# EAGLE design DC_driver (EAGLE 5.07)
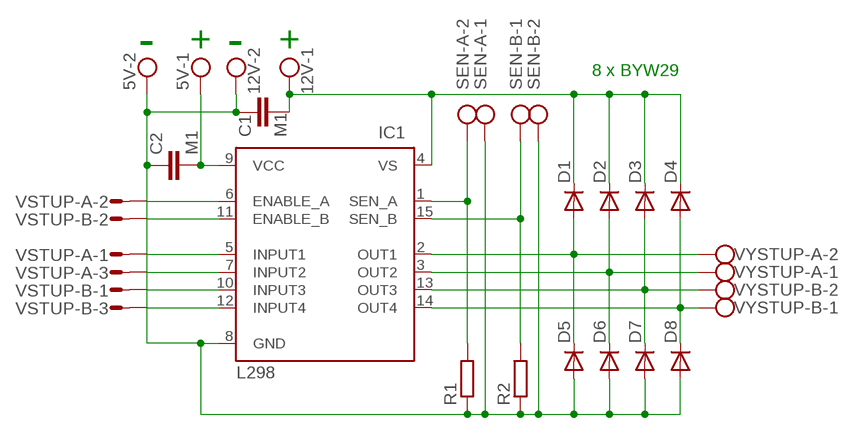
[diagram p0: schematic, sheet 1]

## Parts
5V  W237-102  [W237-102]
12V  W237-102  [W237-102]
C1  M1  C-EU025-025X050  [C025-025X050]
C2  M1  C-EU025-025X050  [C025-025X050]
D1  BYW29  [DO220S]
D2  BYW29  [DO220S]
D3  BYW29  [DO220S]
D4  BYW29  [DO220S]
D5  BYW29  [DO220S]
D6  BYW29  [DO220S]
D7  BYW29  [DO220S]
D8  BYW29  [DO220S]
IC1  L298  [MULTIWATT-15]
R1  R-EU_0411/15  [0411/15]
R2  R-EU_0411/15  [0411/15]
SEN-A  W237-102  [W237-102]
SEN-B  W237-102  [W237-102]
VSTUP-A  M03S  [03P]
VSTUP-B  M03S  [03P]
VYSTUP-A  W237-102  [W237-102]
VYSTUP-B  W237-102  [W237-102]

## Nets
N$1: 12V.1 C1.2 D1.C D2.C D3.C D4.C IC1.4(VS)
N$2: IC1.10(INPUT3) VSTUP-B.1
N$3: IC1.7(INPUT2) VSTUP-A.3
N$4: IC1.5(INPUT1) VSTUP-A.1
N$5: IC1.11(ENABLE_B) VSTUP-B.2
N$6: IC1.6(ENABLE_A) VSTUP-A.2
N$7: IC1.12(INPUT4) VSTUP-B.3
N$9: 5V.2 12V.2 C1.1 C2.1 D5.A D6.A D7.A D8.A IC1.8(GND) R1.1 R2.1 SEN-A.1 SEN-B.2
N$14: IC1.1(SEN_A) R1.2 SEN-A.2
N$15: IC1.15(SEN_B) R2.2 SEN-B.1
N$16: 5V.1 C2.2 IC1.9(VCC)
N$20: D1.A D5.C IC1.2(OUT1) VYSTUP-A.2
N$21: D2.A D6.C IC1.3(OUT2) VYSTUP-A.1
N$22: D3.A D7.C IC1.13(OUT3) VYSTUP-B.2
N$23: D4.A D8.C IC1.14(OUT4) VYSTUP-B.1

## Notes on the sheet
- - | + | - | +
- 8 x BYW29

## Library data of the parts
5V 12V SEN-A SEN-B VYSTUP-A VYSTUP-B = con-wago-500:W237-102: WAGO SCREW CLAMP
C1 C2 = rcl:C-EU: CAPACITOR, European symbol
D1-D8 = diode:BYW29: DIODE
IC1 = st-microelectronics:L298: DUAL FULL-BRIDGE DRIVER
R1 R2 = rcl:R-EU_: RESISTOR, European symbol
VSTUP-A VSTUP-B = con-amp-quick:M03S: AMP QUICK CONNECTOR

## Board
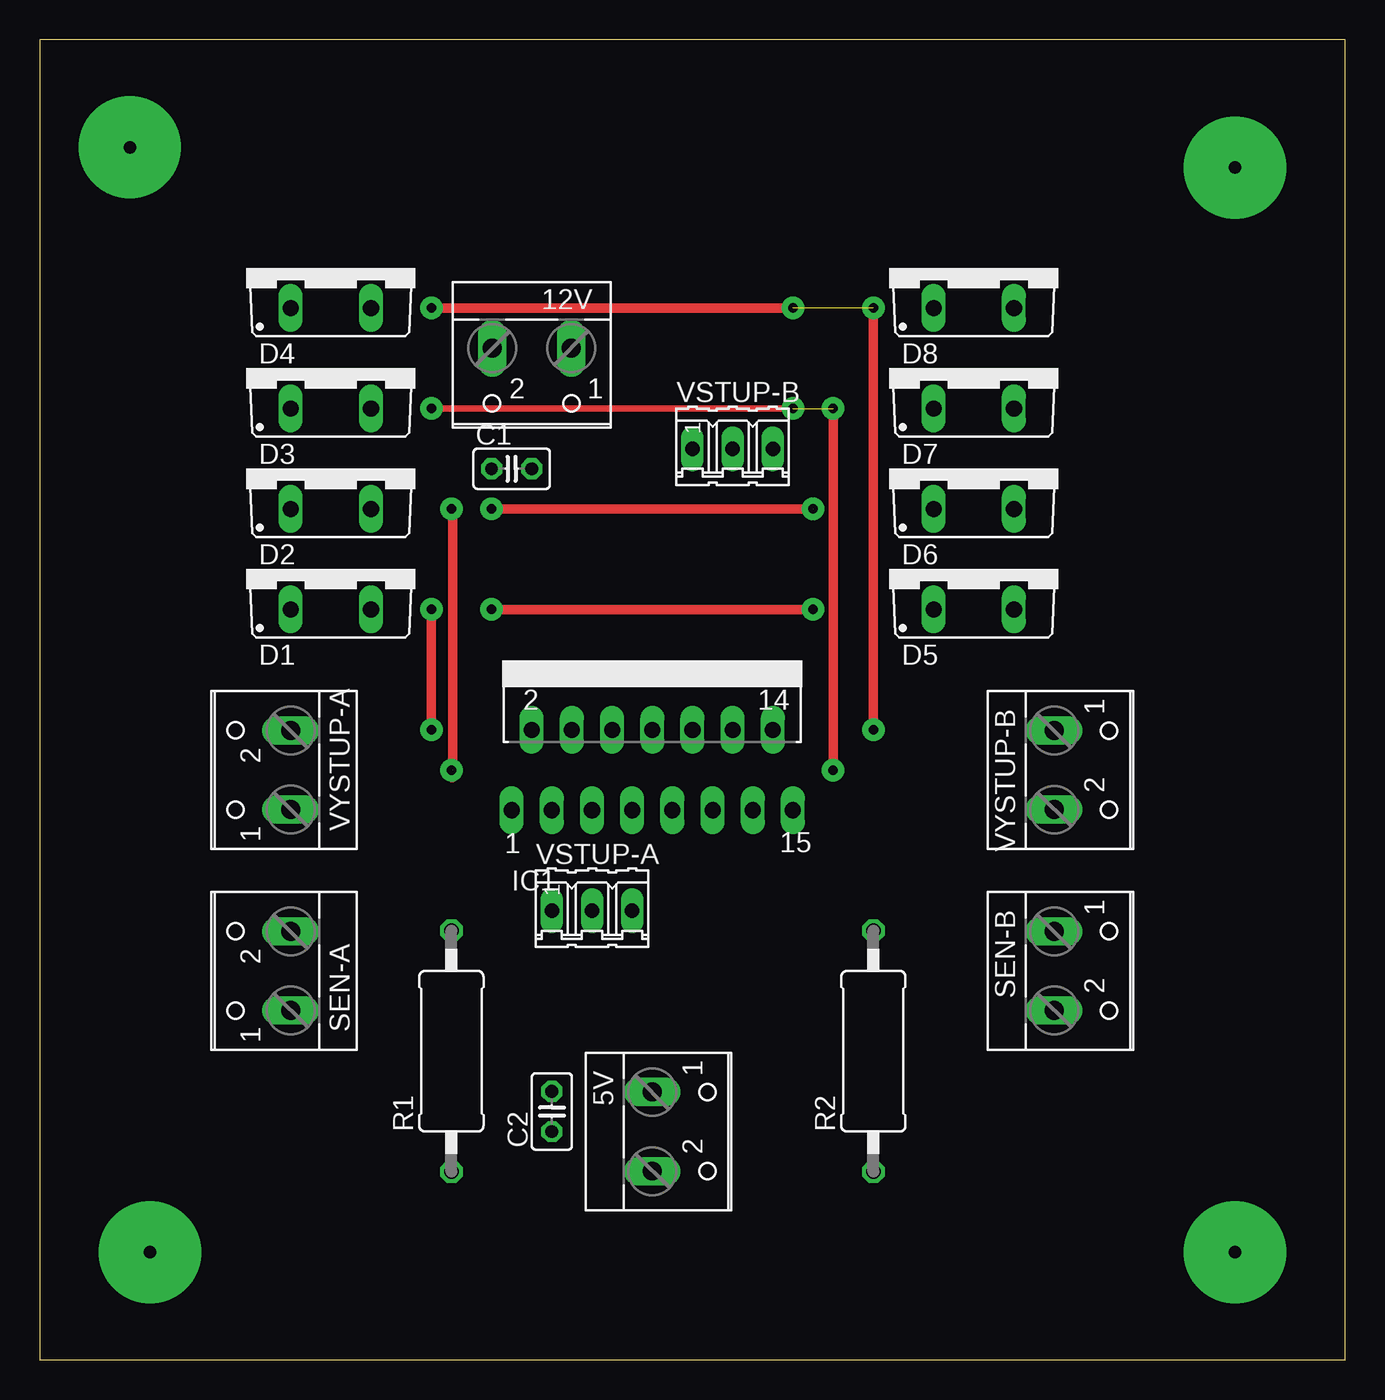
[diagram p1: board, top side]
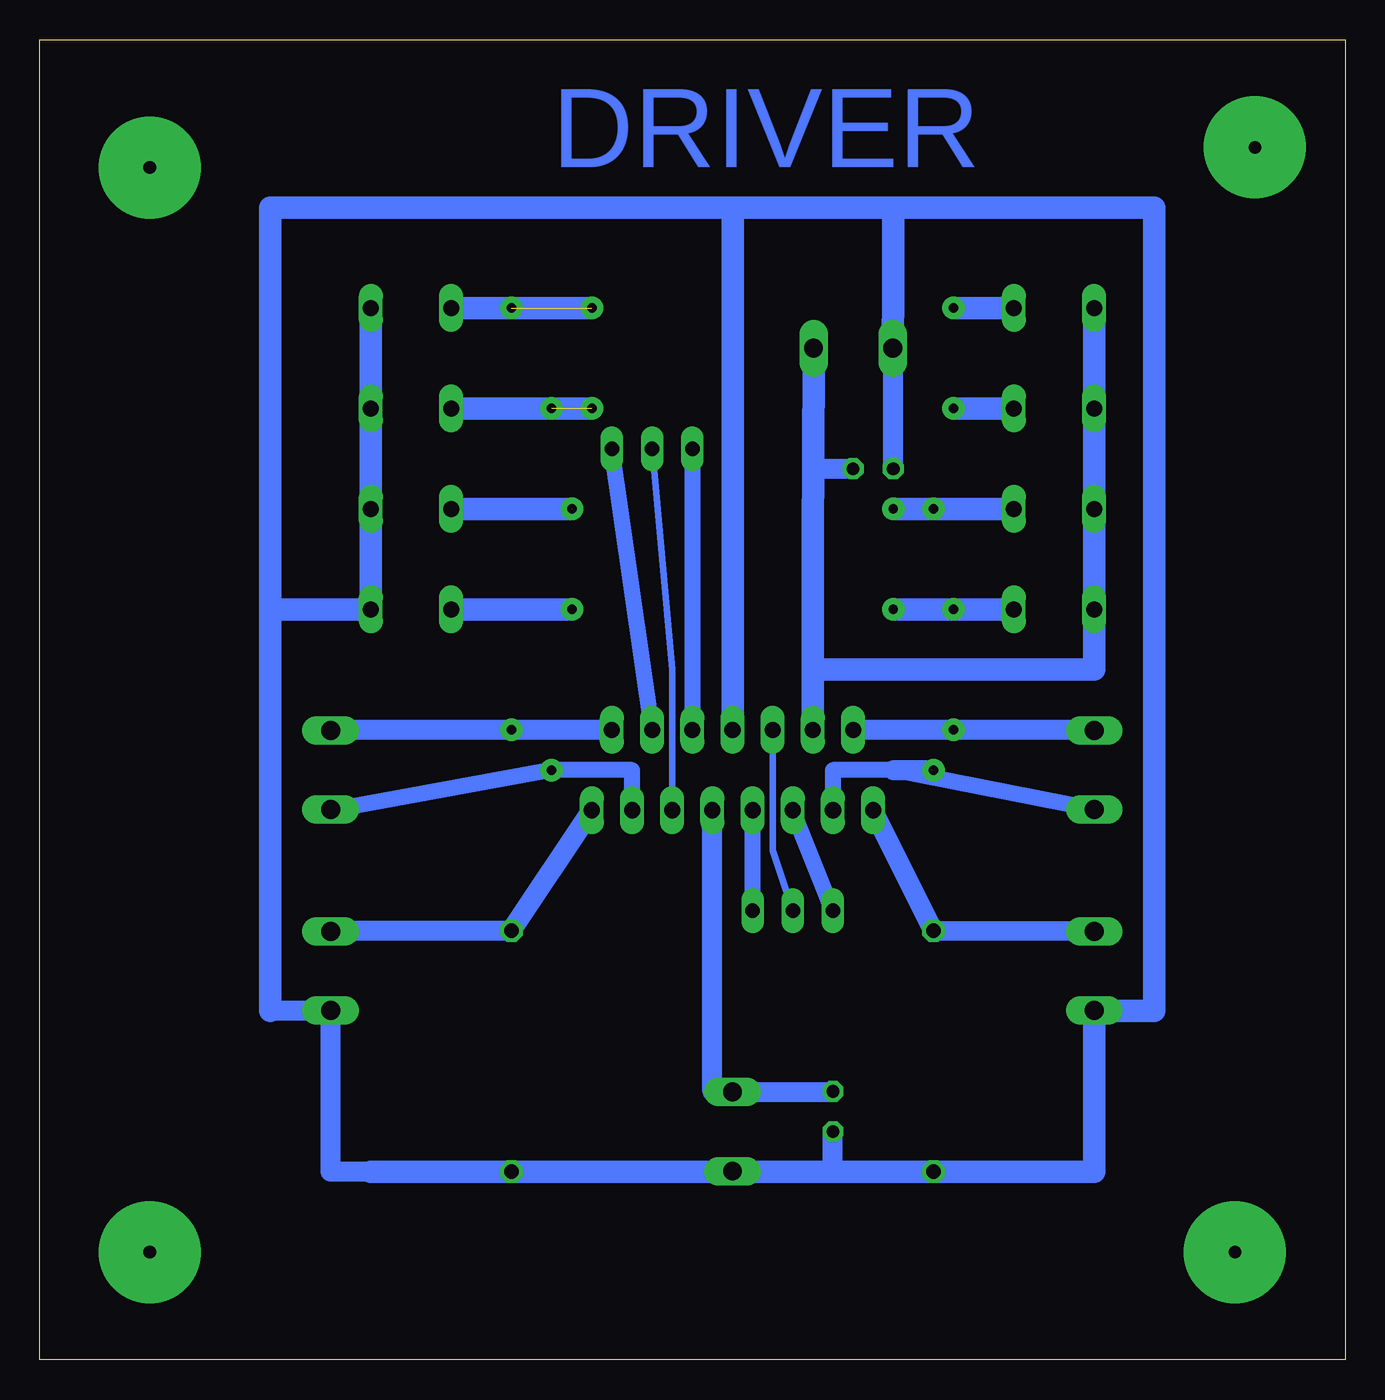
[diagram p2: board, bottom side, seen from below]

Size 82.53 x 83.49 mm. Coordinates in mm from the lower left corner, seen from the top.
Outline: 0,0 82.53,0 82.53,83.49 0,83.49 0,0
Copper layers (1*16): Top 0.035mm / dielectric 1.5mm / Bottom 0.035mm
Design rules "default": minimum track width 10mil, minimum drill 24mil, track to track 8mil, track to pad 8mil, pad to pad 8mil, via to via 8mil, smd to smd 8mil, copper to edge 40mil, drill to drill 8mil, minimum pad ring 10mil, minimum via ring 8mil, stop-mask expansion 4mil, vias tented up to drill 0mil, thermal gap 10mil

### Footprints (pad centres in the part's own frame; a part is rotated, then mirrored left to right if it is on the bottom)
W237-102 = drill 1.194 long: 1 -2.5,-1.27; 2 2.5,-1.27
C025-025X050 = drill 0.813 octagon: 1 -1.27,0; 2 1.27,0
DO220S = drill 1.016 long: A 2.54,-2.54; C -2.54,-2.54
MULTIWATT-15 = drill 1.016 long: 1 -8.89,-7.62; 2 -7.62,-2.54; 3 -6.35,-7.62; 4 -5.08,-2.54; 5 -3.81,-7.62; 6 -2.54,-2.54; 7 -1.27,-7.62; 8 0,-2.54; 9 1.27,-7.62; 10 2.54,-2.54; 11 3.81,-7.62; 12 5.08,-2.54; 13 6.35,-7.62; 14 7.62,-2.54; 15 8.89,-7.62
0411/15 = drill 0.914 octagon: 1 -7.62,0; 2 7.62,0
03P = drill 0.914 long: 1 -2.54,0; 2 0,0; 3 2.54,0

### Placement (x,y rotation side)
5V  40,14.44 270 top
12V  31.11,62.7 180 top
C1  29.84,56.35 0 top
C2  32.38,15.71 90 top
D1  18.41,50 0 top
D2  18.41,56.35 0 top
D3  18.41,62.7 0 top
D4  18.41,69.05 0 top
D5  59.05,50 0 top
D6  59.05,56.35 0 top
D7  59.05,62.7 0 top
D8  59.05,69.05 0 top
IC1  38.73,42.38 0 top
R1  26.03,19.52 90 top
R2  52.7,19.52 90 top
SEN-A  14.6,24.6 90 top
SEN-B  65.4,24.6 270 top
VSTUP-A  34.92,28.41 0 top
VSTUP-B  43.81,57.62 0 top
VYSTUP-A  14.6,37.3 90 top
VYSTUP-B  65.4,37.3 270 top

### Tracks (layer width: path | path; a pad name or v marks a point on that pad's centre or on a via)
N$1
  Bottom 1.27: C1.2 33.64,56.35
  Bottom 1.422: 12V.1 33.64,56.35 33.65,52.54 33.65,43.65 | 33.65,43.65 IC1.4 | 33.65,43.65 15.87,43.65 D1.C D2.C D3.C D4.C
N$2
  Bottom 1.016: 41.27,51.27 VSTUP-B.1 IC1.10
N$3
  Bottom 1.016: VSTUP-A.3 IC1.7
N$4
  Bottom 1.016: VSTUP-A.1 IC1.5
N$5
  Bottom 0.406: IC1.11 42.54,43.65 VSTUP-B.2
N$6
  Bottom 0.406: IC1.6 36.19,32.22 VSTUP-A.2
N$7
  Bottom 1.016: IC1.12 VSTUP-B.3
N$8  (via drill 0.8 pad 6.45)
  other vias: 5.71,76.67
N$9
  Bottom 1.27: 64.13,22.06 64.13,11.9 61.59,11.9 | 64.13,22.06 SEN-B.2 | 64.13,22.06 67.94,22.06 | C1.1 28.61,56.35 12V.2 | 32.38,11.9 C2.1
  Bottom 1.422: 38.73,72.86 IC1.8 | 28.57,72.86 38.73,72.86 | 12V.2 28.57,67.78 28.57,72.86 | 28.57,72.86 12.06,72.86 12.06,22.06 15.87,22.06 | 15.87,22.06 SEN-A.1 | 15.87,22.06 15.87,11.9 R1.1 32.38,11.9 38.73,11.9 | 38.73,11.9 5V.2 | 38.73,11.9 R2.1 61.59,11.9 | 67.94,47.46 67.94,22.06 | 67.94,47.46 67.94,72.86 38.73,72.86 | 67.94,47.46 D5.A D6.A D7.A D8.A
N$10  (via drill 0.6 pad 1.42)
  other vias: 26.03,37.3
N$11  (via drill 0.6 pad 1.42)
  other vias: 24.76,47.46
N$12  (via drill 0.6 pad 1.42)
  other vias: 28.57,47.46
N$13  (via drill 0.6 pad 1.42)
  other vias: 26.03,53.81
N$14
  Bottom 1.27: SEN-A.2 R1.2 IC1.1
N$15
  Bottom 1.27: IC1.15 R2.2 64.13,27.14 SEN-B.1
N$16
  Bottom 1.27: IC1.9 40,16.98 38.73,16.98 5V.1 32.38,16.94 C2.2
N$17  (via drill 0.8 pad 6.45)
  other vias: 75.56,75.4
N$18  (via drill 0.8 pad 6.45)
  other vias: 75.56,6.82
N$19  (via drill 0.8 pad 6.45)
  other vias: 6.98,6.82
N$20  (via drill 0.6 pad 1.42)
  Top 0.61: v24.76,39.84 v24.76,47.46 | v28.57,47.46 v48.89,47.46
  Bottom 1.27: VYSTUP-A.2 17.14,39.84 v24.76,39.84 IC1.2
  Bottom 1.422: v48.89,47.46 D5.C | D1.A v24.76,47.46 v28.57,47.46
N$21  (via drill 0.6 pad 1.42)  (1 unrouted)
  Top 0.61: v26.03,53.81 26.12,53.81 26.12,36.82 26.03,36.82 26.03,37.3 | v28.57,53.81 v48.89,53.81
  Bottom 1.016: VYSTUP-A.1 28.57,37.3 32.38,37.3 IC1.3
  Bottom 1.27: 28.57,37.3 26.12,37.3
  Bottom 1.422: v28.57,53.81 v26.03,53.81 D2.A | v48.89,53.81 D6.C
N$22  (via drill 0.6 pad 1.42)  (3 unrouted)
  Top 0.406: v24.76,60.16 47.62,60.16
  Top 0.61: v50.16,37.3 50.16,60.16
  Bottom 1.016: IC1.13 45.08,37.3 v50.16,37.3 64.13,34.76 VYSTUP-B.2
  Bottom 1.422: v24.76,60.16 D3.A | 47.62,60.16 D7.C
N$23  (via drill 0.6 pad 1.42)  (1 unrouted)
  Top 0.61: v47.62,66.51 v24.76,66.51 | v52.7,39.84 v52.7,66.51
  Bottom 1.27: VYSTUP-B.1 64.13,39.84 v52.7,39.84 IC1.14
  Bottom 1.422: v24.76,66.51 D4.A | v47.62,66.51 v52.7,66.51 D8.C
N$24  (via drill 0.6 pad 1.42)
  other vias: 28.57,53.81
N$25  (via drill 0.6 pad 1.42)
  other vias: 48.89,47.46
N$26  (1 unrouted)
N$27  (via drill 0.6 pad 1.42)
  other vias: 50.16,60.16
N$28  (1 unrouted)
N$29  (via drill 0.6 pad 1.42)
  other vias: 24.76,60.16
N$30  (via drill 0.6 pad 1.42)
  other vias: 24.76,66.51
N$31  (via drill 0.6 pad 1.42)
  other vias: 47.62,60.16
N$32  (1 unrouted)

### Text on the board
Bottom: DRIVER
